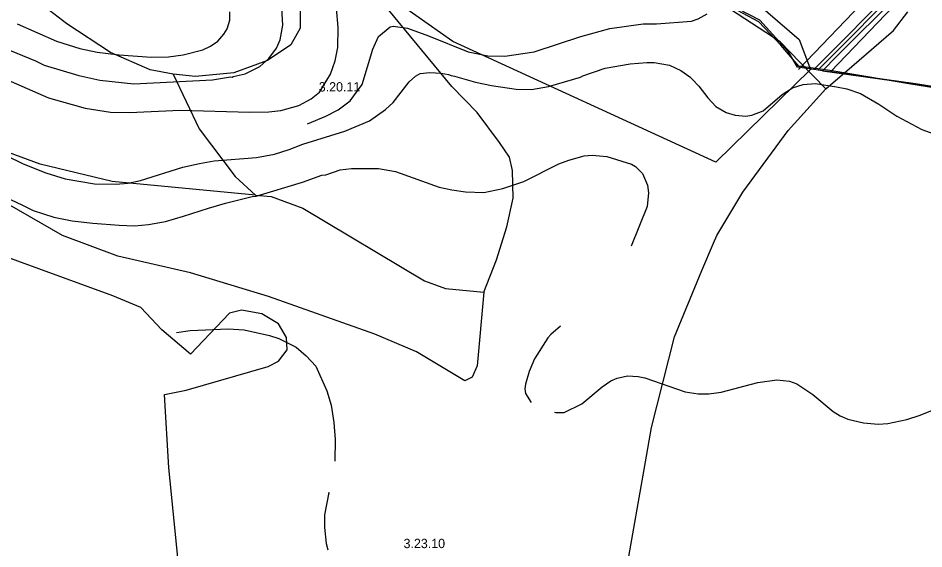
# Model space of a CAD drawing. Extents: x -662500 to -653478, y -1056827 to -1049993.
# Drawn here: x -661377 to -660647, y -1053980 to -1053552 of the extents above; entities that cross this region are included whole.
import ezdxf

# ---------------------------------------------------------------- set-up
doc = ezdxf.new("R2010")
doc.units = 0
for name, color, linetype in [('58', 7, 'Continuous'), ('Vrstva 1', 7, 'Continuous'), ('Vrstva 24', 7, 'Continuous'), ('Vrstva 32', 7, 'Continuous'), ('Vrstva 37', 7, 'Continuous'), ('Vrstva 5', 7, 'Continuous'), ('Vrstva 51', 7, 'Continuous'), ('Vrstva 7', 7, 'Continuous')]:
    doc.layers.add(name, color=color, linetype=linetype)

msp = doc.modelspace()

# ---------------------------------------------------------------- linework, layer by layer
at = {"layer": '58'}
msp.add_lwpolyline([(-660635.87, -1053609.1), (-660659.17, -1053605.23), (-660692.27, -1053599.72), (-660722.92, -1053594.62), (-660747.91, -1053591.01), (-660762.26, -1053574.33), (-660780.1, -1053555.32), (-660805.82, -1053541.62)], dxfattribs=at)
at = {"layer": 'Vrstva 1'}
for points in [[(-660749.01, -1053592.05), (-660756.28, -1053579.6), (-660779.23, -1053554.07), (-660805.9, -1053540.3)], [(-660438.94, -1053983.58), (-660410.34, -1053829.44), (-660408.79, -1053821.07), (-660408.56, -1053819.81), (-660407.77, -1053814.99), (-660398.86, -1053759.98), (-660378.28, -1053653.76), (-660412.36, -1053647.26), (-660481.41, -1053634.1), (-660522.43, -1053627.05), (-660591.82, -1053615.12), (-660653.75, -1053605.31), (-660728.84, -1053594.86), (-660735.74, -1053593.9), (-660749.01, -1053592.05)]]:
    msp.add_lwpolyline(points, dxfattribs=at)
at = {"layer": 'Vrstva 24'}
for points in [[(-661088, -1053355.5), (-661106, -1053352.5), (-661119, -1053355), (-661133.5, -1053361.5), (-661158.5, -1053380.5), (-661171.5, -1053398.5), (-661180, -1053425.5), (-661178.5, -1053461.5), (-661169.5, -1053488.5), (-661160, -1053506.5), (-661149.5, -1053542.5), (-661149.5, -1053560.5), (-661157, -1053574), (-661176, -1053586.5), (-661203, -1053596.5), (-661234, -1053599.5), (-661252, -1053597.5)], [(-661001.5, -1053773), (-660991.5, -1053747), (-660983, -1053720.5), (-660978, -1053697.5), (-660978.5, -1053675), (-660981, -1053664.5), (-660989, -1053652.5), (-661007, -1053628.5), (-661027.5, -1053607.5), (-661079.5, -1053544.5), (-661099.5, -1053509.5), (-661117, -1053463.5), (-661120.5, -1053436.5), (-661117, -1053400.5), (-661107.5, -1053378), (-661096, -1053362.5), (-661088, -1053355.5)], [(-660726, -1053609.5), (-660746.75, -1053588.19), (-660763, -1053571.5), (-660803, -1053545.5), (-660863.5, -1053530), (-660875.5, -1053525), (-660916, -1053497.5), (-660931, -1053485.5)], [(-661252, -1053597.5), (-661270.5, -1053594), (-661302.5, -1053580), (-661337.5, -1053557), (-661355, -1053543.5), (-661366, -1053538), (-661385, -1053533.5)], [(-660726, -1053609.5), (-660705.14, -1053591.51), (-660671.5, -1053562.5), (-660660, -1053547.5)], [(-661185.5, -1053695), (-661301, -1053684), (-661359, -1053670), (-661461.5, -1053632.5), (-661511.5, -1053619), (-661574.5, -1053608), (-661636, -1053600.5), (-661701, -1053596.5), (-661815.5, -1053587.5), (-661858, -1053587.5)], [(-661252, -1053597.5), (-661231, -1053641.5), (-661202, -1053680), (-661185.5, -1053695)], [(-660911, -1054178.5), (-660888, -1054130), (-660876.5, -1054089.5), (-660875.5, -1054053.5), (-660883, -1054011.5), (-660884.37, -1054000), (-660885.5, -1053990.5), (-660872.42, -1053915.83), (-660866.5, -1053882), (-660848, -1053809), (-660826, -1053755.5), (-660816.62, -1053733.62), (-660814, -1053727.5), (-660793, -1053692.5), (-660756.5, -1053643), (-660726, -1053609.5)], [(-661001.5, -1053773), (-661007, -1053832.5), (-661011, -1053841.5), (-661017, -1053844.5), (-661056, -1053821), (-661089.5, -1053807), (-661175, -1053776.5), (-661238, -1053757.5), (-661296.5, -1053744), (-661341, -1053727.5), (-661428, -1053677.5), (-661441.5, -1053671.5), (-661457, -1053664.5), (-661466, -1053663), (-661476, -1053660.5), (-661516, -1053659.5), (-661560.5, -1053660.5), (-661618.5, -1053666.5), (-661717, -1053683.5), (-661723, -1053683.5)], [(-661246.7, -1054000), (-661255.5, -1053914.5), (-661259, -1053855.5), (-661241.5, -1053852), (-661175.5, -1053833), (-661167, -1053828.5), (-661160, -1053819.5), (-661160.5, -1053809.5), (-661167, -1053798.5), (-661180.5, -1053790.5), (-661197, -1053787.5), (-661206.5, -1053790), (-661238, -1053823), (-661261, -1053803.5), (-661278, -1053785.5), (-661300.5, -1053776), (-661437, -1053726.5), (-661515.5, -1053701.5), (-661544, -1053699.5), (-661598, -1053702.5), (-661562, -1053690.5), (-661657, -1053696.5), (-661706, -1053697)], [(-661185.5, -1053695), (-661173, -1053696), (-661147.5, -1053705.5), (-661049.5, -1053764), (-661032.5, -1053770), (-661001.5, -1053773)]]:
    msp.add_lwpolyline(points, dxfattribs=at)
at = {"layer": 'Vrstva 32'}
msp.add_lwpolyline([(-660732.59, -1053594.34), (-660658.93, -1053520.19), (-660602.39, -1053463.45), (-660566.95, -1053428.59), (-660489, -1053349.86), (-660473.49, -1053335.13), (-660419.3, -1053279.86), (-660364.42, -1053224.74), (-660340.86, -1053200.88), (-660320.07, -1053179.63)], dxfattribs=at)
at = {"layer": 'Vrstva 37'}
msp.add_lwpolyline([(-661177.27, -1053298.13), (-661011.27, -1053272.33), (-660950.35, -1053416.85), (-660917.78, -1053483.08), (-660790.25, -1053532.64), (-660747.55, -1053569.67), (-660738.48, -1053593.77), (-660814.61, -1053668.4), (-661026.54, -1053571.34), (-661076.33, -1053536.24), (-661164.49, -1053527.45), (-661164.49, -1053425.3)], close=True, dxfattribs=at)
at = {"layer": 'Vrstva 5'}
for points in [[(-660621.85, -1053488.15), (-660667.78, -1053533.76), (-660717.01, -1053582.82), (-660728.84, -1053594.86), (-660735.74, -1053593.9), (-660718.56, -1053576.57), (-660650.77, -1053508.27), (-660618.91, -1053475.06)], [(-660621.85, -1053488.15), (-660667.78, -1053533.76), (-660717.01, -1053582.82), (-660728.84, -1053594.86), (-660659.38, -1053604.53), (-660591.82, -1053615.12)], [(-660650.77, -1053508.27), (-660718.56, -1053576.57), (-660735.74, -1053593.9), (-660749.01, -1053592.05), (-660756.28, -1053579.6), (-660779.23, -1053554.07), (-660805.9, -1053540.3)]]:
    msp.add_lwpolyline(points, dxfattribs=at)
at = {"layer": 'Vrstva 51'}
for points in [[(-660413.11, -1053292.08), (-660549.62, -1053432.47), (-660602.23, -1053470.43), (-660722.2, -1053595.78)], [(-660747.98, -1053593.81), (-660615.41, -1053455.28), (-660562.74, -1053417.28), (-660448.34, -1053299.63)]]:
    msp.add_lwpolyline(points, dxfattribs=at)
at = {"layer": 'Vrstva 7'}
for p, q in [((-661163.58, -1053558.13), (-661164.29, -1053544.52)), ((-661119.08, -1053560.11), (-661120.21, -1053544.52)), ((-661206.38, -1053554.16), (-661206.23, -1053547.35)), ((-660834.23, -1053555.01), (-660828.84, -1053553.02)), ((-660828.84, -1053553.02), (-660821.76, -1053549.06)), ((-661377.57, -1053556.99), (-661345.83, -1053570.88)), ((-661208.36, -1053560.96), (-661206.38, -1053554.16)), ((-661165.85, -1053570.03), (-661163.58, -1053558.13)), ((-661119.36, -1053575.98), (-661119.08, -1053560.11)), ((-661086.48, -1053567.2), (-661076.99, -1053559.54)), ((-661076.99, -1053559.54), (-661074.58, -1053558.98)), ((-661074.58, -1053558.98), (-661063.1, -1053560.53)), ((-661063.1, -1053560.53), (-661046.09, -1053566.63)), ((-660899.99, -1053560.82), (-660873.34, -1053557.13)), ((-660873.34, -1053557.13), (-660862.58, -1053557.06)), ((-660862.58, -1053557.06), (-660834.23, -1053555.01)), ((-661216.01, -1053570.88), (-661211.05, -1053565.5)), ((-661211.05, -1053565.5), (-661208.36, -1053560.96)), ((-661091.02, -1053577.4), (-661086.48, -1053567.2)), ((-661046.09, -1053566.63), (-661014.21, -1053579.67)), ((-660961.07, -1053579.52), (-660923.51, -1053567.34)), ((-660923.51, -1053567.34), (-660899.99, -1053560.82)), ((-661393.3, -1053574.56), (-661362.83, -1053586.89)), ((-661345.83, -1053570.88), (-661327.12, -1053576.97)), ((-661227.92, -1053578.11), (-661221.97, -1053575.13)), ((-661221.97, -1053575.13), (-661216.01, -1053570.88)), ((-661168.78, -1053576.77), (-661165.85, -1053570.03)), ((-661327.12, -1053576.97), (-661313.23, -1053579.81)), ((-661313.23, -1053579.81), (-661295.38, -1053582.08)), ((-661295.38, -1053582.08), (-661269.58, -1053583.92)), ((-661255.69, -1053583.49), (-661243.79, -1053581.93)), ((-661243.79, -1053581.93), (-661227.92, -1053578.11)), ((-661174.77, -1053584.91), (-661168.78, -1053576.77)), ((-661121.49, -1053586.75), (-661119.36, -1053575.98)), ((-661099.66, -1053605.88), (-661091.02, -1053577.4)), ((-661014.21, -1053579.67), (-660998.34, -1053582.78)), ((-660984.73, -1053583.21), (-660961.07, -1053579.52)), ((-661362.83, -1053586.89), (-661355.89, -1053590.29)), ((-661269.58, -1053583.92), (-661255.69, -1053583.49)), ((-661182, -1053591.29), (-661174.77, -1053584.91)), ((-661125.17, -1053597.52), (-661121.49, -1053586.75)), ((-660998.34, -1053582.78), (-660984.73, -1053583.21)), ((-660903.95, -1053592.85), (-660883.83, -1053589.16)), ((-660883.83, -1053589.16), (-660870.22, -1053588.17)), ((-660870.22, -1053588.17), (-660864.27, -1053588.31)), ((-660864.27, -1053588.31), (-660852.09, -1053590.44)), ((-661355.89, -1053590.29), (-661327.97, -1053598.66)), ((-661203.68, -1053599.36), (-661193.91, -1053597.24)), ((-661193.91, -1053597.24), (-661182, -1053591.29)), ((-661056.58, -1053599.22), (-661053.04, -1053597.1)), ((-661053.04, -1053597.1), (-661045.1, -1053596.25)), ((-661045.1, -1053596.25), (-661036.03, -1053596.81)), ((-661036.03, -1053596.81), (-661030.08, -1053597.95)), ((-660921.81, -1053598.8), (-660903.95, -1053592.85)), ((-660852.09, -1053590.44), (-660843.02, -1053594.55)), ((-660843.02, -1053594.55), (-660835.78, -1053599.76)), ((-661386.64, -1053601.63), (-661352.34, -1053616.65)), ((-661327.97, -1053598.66), (-661310.96, -1053602.48)), ((-661310.96, -1053602.48), (-661283.75, -1053605.32)), ((-661283.75, -1053605.32), (-661220.27, -1053602.06)), ((-661220.27, -1053602.06), (-661205.81, -1053599.79)), ((-661205.81, -1053599.79), (-661204.53, -1053600.07)), ((-661204.53, -1053600.07), (-661203.68, -1053599.36)), ((-661134.1, -1053611.98), (-661125.17, -1053597.52)), ((-661074.72, -1053620.34), (-661061.83, -1053603.76)), ((-661061.83, -1053603.76), (-661056.58, -1053599.22)), ((-661030.08, -1053597.95), (-661027.99, -1053598.52)), ((-661027.99, -1053598.52), (-661025.26, -1053599.08)), ((-661025.26, -1053599.08), (-661008.26, -1053604.04)), ((-661008.26, -1053604.04), (-660995.5, -1053606.73)), ((-660949.59, -1053607.44), (-660923.79, -1053599.93)), ((-660923.79, -1053599.93), (-660921.81, -1053598.8)), ((-660835.78, -1053599.76), (-660833.38, -1053601.92)), ((-660833.38, -1053601.92), (-660828.42, -1053607.16)), ((-661109.3, -1053618.92), (-661099.66, -1053605.88)), ((-660995.5, -1053606.73), (-660975.66, -1053609.57)), ((-660975.66, -1053609.57), (-660963.19, -1053609.99)), ((-660963.19, -1053609.99), (-660949.59, -1053607.44)), ((-660828.42, -1053607.16), (-660821.19, -1053616.51)), ((-660761.32, -1053613.94), (-660752.83, -1053608.65)), ((-660752.83, -1053608.65), (-660744.22, -1053605.78)), ((-660744.22, -1053605.78), (-660734.53, -1053605.06)), ((-660734.53, -1053605.06), (-660717.45, -1053607.87)), ((-660717.45, -1053607.87), (-660709.23, -1053609.43)), ((-660709.23, -1053609.43), (-660698.18, -1053613.11)), ((-661352.34, -1053616.65), (-661322.87, -1053625.02)), ((-661150.82, -1053622.75), (-661140.62, -1053617.51)), ((-661140.62, -1053617.51), (-661134.1, -1053611.98)), ((-661119.08, -1053626.29), (-661109.3, -1053618.92)), ((-660821.19, -1053616.51), (-660814.67, -1053623.6)), ((-660776.69, -1053627), (-660761.32, -1053613.94)), ((-660698.18, -1053613.11), (-660683.3, -1053621.61)), ((-661322.87, -1053625.02), (-661302.46, -1053628.27)), ((-661165.28, -1053626.72), (-661150.82, -1053622.75)), ((-661129, -1053631.25), (-661119.08, -1053626.29)), ((-661093.71, -1053635.15), (-661080.96, -1053626.01)), ((-661080.96, -1053626.01), (-661074.72, -1053620.34)), ((-660814.67, -1053623.6), (-660806.45, -1053628.42)), ((-660683.3, -1053621.61), (-660668.85, -1053631.39)), ((-661302.46, -1053628.27), (-661287.16, -1053628.56)), ((-661287.16, -1053628.56), (-661246.34, -1053626.57)), ((-661246.34, -1053626.57), (-661190.22, -1053628.13)), ((-661190.22, -1053628.13), (-661174.92, -1053627.85)), ((-661174.92, -1053627.85), (-661165.28, -1053626.72)), ((-661143.74, -1053637.42), (-661129, -1053631.25)), ((-660806.45, -1053628.42), (-660799.08, -1053630.68)), ((-660799.08, -1053630.68), (-660790.58, -1053631.25)), ((-660790.58, -1053631.25), (-660785.76, -1053630.54)), ((-660785.76, -1053630.54), (-660776.69, -1053627)), ((-660668.85, -1053631.39), (-660648.86, -1053642.02)), ((-661113.57, -1053643.53), (-661093.71, -1053635.15)), ((-661147.42, -1053653.85), (-661113.57, -1053643.53)), ((-660648.86, -1053642.02), (-660627.61, -1053649.82)), ((-661158.48, -1053658.18), (-661147.42, -1053653.85)), ((-661184.84, -1053664.55), (-661170.38, -1053661.86)), ((-661170.38, -1053661.86), (-661158.48, -1053658.18)), ((-660920.68, -1053663.42), (-660914.44, -1053662.85)), ((-660914.44, -1053662.85), (-660902.54, -1053663.85)), ((-661386.36, -1053663), (-661372.75, -1053669.66)), ((-661372.75, -1053669.66), (-661354.61, -1053676.88)), ((-661244.21, -1053672.49), (-661230.75, -1053669.37)), ((-661230.75, -1053669.37), (-661218.85, -1053667.39)), ((-661218.85, -1053667.39), (-661184.84, -1053664.55)), ((-660969.43, -1053683.97), (-660941.08, -1053669.8)), ((-660941.08, -1053669.8), (-660933.15, -1053666.68)), ((-660933.15, -1053666.68), (-660920.68, -1053663.42)), ((-660902.54, -1053663.85), (-660882.62, -1053670.15)), ((-660882.62, -1053670.15), (-660879.3, -1053671.92)), ((-661354.61, -1053676.88), (-661339.02, -1053681.84)), ((-661278.37, -1053683.26), (-661244.21, -1053672.49)), ((-661128.86, -1053678.58), (-661117.39, -1053674.67)), ((-661117.39, -1053674.67), (-661108.12, -1053673.47)), ((-661108.12, -1053673.47), (-661086.48, -1053673.62)), ((-661086.48, -1053673.62), (-661072.74, -1053676.03)), ((-661072.74, -1053676.03), (-661037.73, -1053688.5)), ((-660879.3, -1053671.92), (-660873.77, -1053677.59)), ((-661339.02, -1053681.84), (-661315.21, -1053685.81)), ((-661288.29, -1053685.25), (-661278.37, -1053683.26)), ((-661184.98, -1053695.87), (-661147.71, -1053684.54)), ((-661147.71, -1053684.54), (-661132.26, -1053678.87)), ((-661132.26, -1053678.87), (-661128.86, -1053678.58)), ((-660986.43, -1053689.5), (-660969.43, -1053683.97)), ((-660873.77, -1053677.59), (-660869.8, -1053686.8)), ((-661315.21, -1053685.81), (-661298.21, -1053686.24)), ((-661298.21, -1053686.24), (-661288.29, -1053685.25)), ((-661037.73, -1053688.5), (-661027.53, -1053690.77)), ((-661027.53, -1053690.77), (-661016.48, -1053692.19)), ((-661001.74, -1053692.76), (-660986.43, -1053689.5)), ((-660869.8, -1053686.8), (-660868.95, -1053693.04)), ((-661387.63, -1053696.44), (-661373.32, -1053702.96)), ((-661209.9, -1053701.32), (-661188.24, -1053696.16)), ((-661188.24, -1053696.16), (-661184.98, -1053695.87)), ((-661016.48, -1053692.19), (-661001.74, -1053692.76)), ((-660868.95, -1053693.04), (-660870.1, -1053704.11)), ((-661373.32, -1053702.96), (-661364.82, -1053707.21)), ((-661243.51, -1053711.75), (-661223.38, -1053705.37)), ((-661223.38, -1053705.37), (-661209.9, -1053701.32)), ((-660870.1, -1053704.11), (-660882.86, -1053736.16)), ((-661364.82, -1053707.21), (-661348.09, -1053712.6)), ((-661348.09, -1053712.6), (-661333.21, -1053715.71)), ((-661258.24, -1053716.28), (-661243.51, -1053711.75)), ((-661333.21, -1053715.71), (-661316.63, -1053717.56)), ((-661316.63, -1053717.56), (-661295.38, -1053719.11)), ((-661295.38, -1053719.11), (-661283.05, -1053719.68)), ((-661283.05, -1053719.68), (-661271.85, -1053718.69)), ((-661271.85, -1053718.69), (-661258.24, -1053716.28)), ((-660939.91, -1053800.41), (-660947.74, -1053807.12)), ((-661249.17, -1053805.44), (-661238.12, -1053804)), ((-661238.12, -1053804), (-661207.51, -1053802.59)), ((-661207.51, -1053802.59), (-661194.76, -1053803.29)), ((-661194.76, -1053803.29), (-661174.35, -1053807.97)), ((-661174.35, -1053807.97), (-661166.7, -1053810.38)), ((-660947.74, -1053807.12), (-660949.96, -1053809.75)), ((-661166.7, -1053810.38), (-661152.95, -1053817.47)), ((-660949.96, -1053809.75), (-660960.92, -1053826.82)), ((-661152.95, -1053817.47), (-661144.73, -1053824.41)), ((-661144.73, -1053824.41), (-661136.94, -1053832.77)), ((-660960.92, -1053826.82), (-660965.18, -1053837.02)), ((-661136.94, -1053832.77), (-661128.15, -1053852.61)), ((-660965.18, -1053837.02), (-660968.15, -1053847.23)), ((-660906.36, -1053849.35), (-660899.42, -1053844.39)), ((-660899.42, -1053844.39), (-660894.32, -1053842.27)), ((-660894.32, -1053842.27), (-660885.81, -1053840.42)), ((-660885.81, -1053840.42), (-660877.31, -1053840.85)), ((-660877.31, -1053840.85), (-660871.93, -1053842.01)), ((-660871.93, -1053842.01), (-660839.33, -1053853.18)), ((-660780.94, -1053845.81), (-660765.64, -1053843.68)), ((-660765.64, -1053843.68), (-660755.44, -1053844.68)), ((-660755.44, -1053844.68), (-660749.48, -1053846.8)), ((-661128.15, -1053852.61), (-661124.75, -1053863.95)), ((-660968.15, -1053847.23), (-660968.58, -1053850.91)), ((-660968.58, -1053850.91), (-660968.15, -1053854.6)), ((-660922.66, -1053862.96), (-660906.36, -1053849.35)), ((-660810.42, -1053853.46), (-660780.94, -1053845.81)), ((-660749.48, -1053846.8), (-660736.45, -1053855.45)), ((-660968.15, -1053854.6), (-660963.53, -1053861.87)), ((-660839.33, -1053853.18), (-660828.84, -1053855.02)), ((-660828.84, -1053855.02), (-660820.34, -1053854.88)), ((-660820.34, -1053854.88), (-660810.42, -1053853.46)), ((-660736.45, -1053855.45), (-660720.29, -1053869.19)), ((-660650, -1053872.03), (-660618.54, -1053859.13)), ((-661124.75, -1053863.95), (-661122.48, -1053878.12)), ((-660936.97, -1053869.9), (-660922.66, -1053862.96)), ((-660944.75, -1053869.77), (-660943.52, -1053869.96)), ((-660943.52, -1053869.96), (-660936.97, -1053869.9)), ((-660720.29, -1053869.19), (-660714.48, -1053872.74)), ((-660714.48, -1053872.74), (-660708.39, -1053875.43)), ((-660660.77, -1053875.57), (-660650, -1053872.03)), ((-661122.48, -1053878.12), (-661121.35, -1053891.73)), ((-660708.39, -1053875.43), (-660695.63, -1053878.26)), ((-660695.63, -1053878.26), (-660683.87, -1053879.26)), ((-660683.87, -1053879.26), (-660676.07, -1053878.69)), ((-660676.07, -1053878.69), (-660660.77, -1053875.57)), ((-661121.35, -1053891.73), (-661121.65, -1053909.19)), ((-661126.45, -1053934.38), (-661130.13, -1053952.38)), ((-661126.31, -1053935.39), (-661126.45, -1053934.38)), ((-661130.13, -1053952.38), (-661129.99, -1053962.58)), ((-661129.99, -1053962.58), (-661128.57, -1053975.34)), ((-661128.57, -1053975.34), (-661127.44, -1053980.44))]:
    msp.add_line(p, q, dxfattribs=at)

# ---------------------------------------------------------------- texts
at = {"layer": 'Vrstva 24'}
for s, p in [('3.20.11', (-661134.62, -1053611.51)), ('3.23.10', (-661066.32, -1053979.11))]:
    msp.add_text(s, height=7.5, dxfattribs=at).set_placement(p)

doc.saveas('drawing.dxf')
